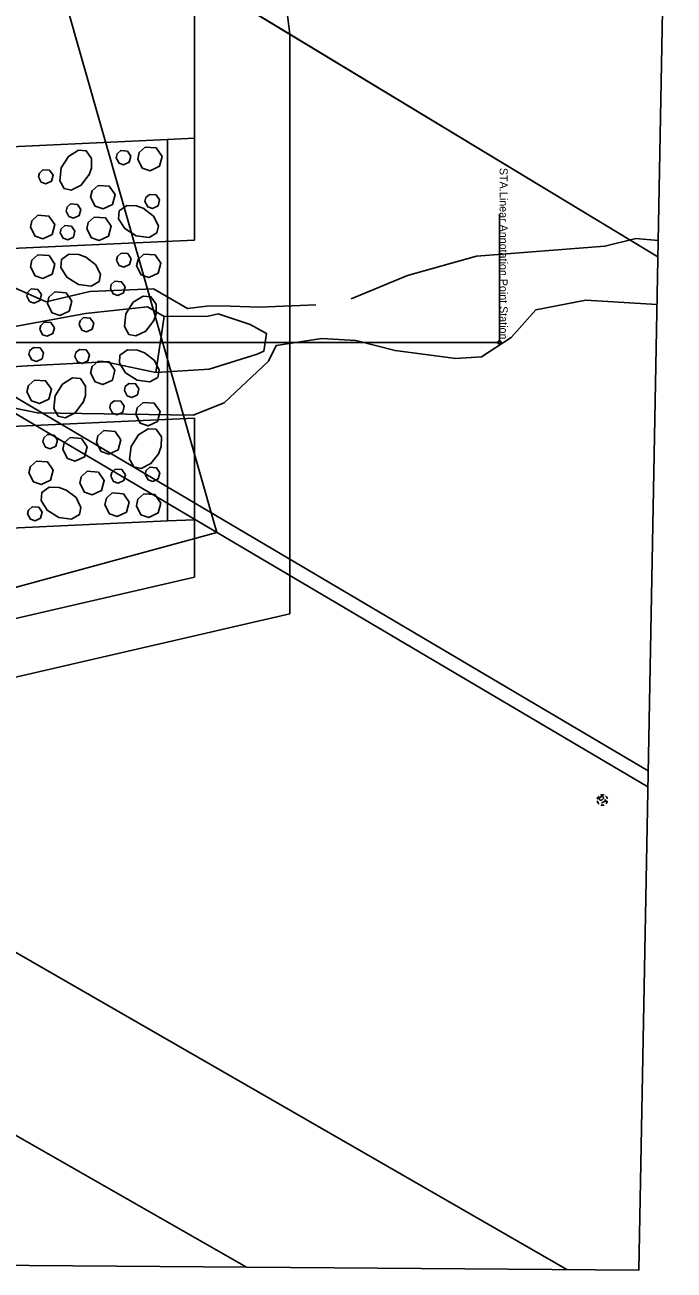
# Model space of a CAD drawing. Extents: x -1609 to 1184, y -412 to 394.
# Drawn here: x 44.9 to 78.9, y 262.3 to 327.7 of the extents above; entities that cross this region are included whole.
import ezdxf

# ---------------------------------------------------------------- set-up
doc = ezdxf.new("R2010")
doc.units = 0
for name, color, linetype in [('DR_P_Erosion_Control', 7, 'Continuous'), ('DT_P_Slope_Break_Line', 7, 'Continuous'), ('DT_X_Slope_Break_Line', 7, 'Continuous'), ('GE_P_Alignment_100_Cardinal_Points', 7, 'Continuous'), ('GE_P_CL_10', 7, 'Continuous'), ('HY_P_Water_Edge', 7, 'Continuous'), ('HY_X_Water_Edge', 7, 'Continuous'), ('PV_P_Shoulder', 7, 'Continuous'), ('RW_P_Const_Limits', 7, 'Continuous'), ('RW_X_Esmt_SH', 7, 'Continuous'), ('SH_Named_Boundary', 7, 'Continuous'), ('UT_X_Oil_Cells', 7, 'Continuous')]:
    doc.layers.add(name, color=color, linetype=linetype)

msp = doc.modelspace()

# ---------------------------------------------------------------- linework, layer by layer
at = {"layer": 'DR_P_Erosion_Control'}
for p, q in [((38.371, 320.994), (52.371, 321.648)), ((52.371, 321.648), (52.371, 301.62)), ((52.37, 312.649), (52.371, 312.649)), ((38.371, 300.989), (52.371, 301.62))]:
    msp.add_line(p, q, dxfattribs=at)
for points in [[(48.246, 319.785), (47.837, 319.247), (47.316, 318.991), (46.946, 319.072), (46.711, 319.478), (46.793, 320.15), (47.178, 320.758), (47.691, 321.081), (48.109, 321.05), (48.387, 320.652), (48.373, 320.139), (48.233, 319.758)], [(49.914, 321.065), (50.264, 321.04), (50.446, 320.774), (50.363, 320.463), (50.068, 320.322), (49.824, 320.407), (49.679, 320.691), (49.726, 320.894), (49.914, 321.064)], [(51.197, 321.244), (51.78, 321.203), (52.084, 320.76), (51.945, 320.241), (51.454, 320.007), (51.046, 320.148), (50.805, 320.621), (50.883, 320.959), (51.197, 321.244)], [(45.834, 320.057), (46.184, 320.033), (46.366, 319.766), (46.283, 319.455), (45.988, 319.314), (45.743, 319.399), (45.599, 319.683), (45.646, 319.886), (45.834, 320.057)], [(48.729, 319.237), (49.312, 319.196), (49.616, 318.753), (49.478, 318.233), (48.986, 317.999), (48.579, 318.141), (48.337, 318.614), (48.415, 318.952), (48.729, 319.237)], [(51.422, 318.767), (51.772, 318.743), (51.954, 318.477), (51.871, 318.165), (51.576, 318.025), (51.331, 318.11), (51.187, 318.394), (51.233, 318.597), (51.422, 318.767)], [(45.568, 317.665), (46.151, 317.625), (46.455, 317.181), (46.317, 316.662), (45.825, 316.428), (45.418, 316.569), (45.176, 317.043), (45.254, 317.381), (45.568, 317.665)], [(47.288, 318.266), (47.638, 318.242), (47.82, 317.975), (47.737, 317.664), (47.442, 317.523), (47.198, 317.608), (47.053, 317.892), (47.1, 318.095), (47.288, 318.266)], [(51.094, 318.038), (51.633, 317.628), (51.889, 317.108), (51.807, 316.738), (51.402, 316.503), (50.73, 316.585), (50.122, 316.969), (49.799, 317.483), (49.83, 317.901), (50.227, 318.179), (50.74, 318.165), (51.121, 318.024)], [(46.979, 317.123), (47.329, 317.099), (47.511, 316.833), (47.428, 316.521), (47.133, 316.381), (46.889, 316.466), (46.744, 316.75), (46.791, 316.953), (46.979, 317.123)], [(48.525, 317.575), (49.108, 317.534), (49.412, 317.091), (49.274, 316.571), (48.782, 316.337), (48.375, 316.478), (48.133, 316.952), (48.212, 317.29), (48.526, 317.575)], [(45.572, 315.588), (46.155, 315.548), (46.459, 315.104), (46.321, 314.585), (45.829, 314.351), (45.421, 314.492), (45.18, 314.965), (45.258, 315.304), (45.572, 315.588)], [(48.065, 315.482), (48.603, 315.073), (48.859, 314.552), (48.777, 314.183), (48.372, 313.948), (47.7, 314.029), (47.092, 314.414), (46.769, 314.928), (46.8, 315.346), (47.197, 315.623), (47.711, 315.609), (48.092, 315.469)], [(49.931, 315.68), (50.281, 315.656), (50.463, 315.39), (50.38, 315.078), (50.085, 314.938), (49.84, 315.023), (49.696, 315.307), (49.743, 315.51), (49.931, 315.68)], [(51.135, 315.631), (51.718, 315.591), (52.022, 315.147), (51.884, 314.628), (51.392, 314.394), (50.984, 314.535), (50.743, 315.009), (50.821, 315.347), (51.135, 315.631)], [(45.223, 313.801), (45.573, 313.777), (45.755, 313.511), (45.672, 313.199), (45.377, 313.059), (45.133, 313.143), (44.988, 313.427), (45.035, 313.631), (45.223, 313.801)], [(49.608, 314.204), (49.957, 314.18), (50.14, 313.913), (50.057, 313.602), (49.762, 313.462), (49.517, 313.546), (49.372, 313.83), (49.419, 314.033), (49.607, 314.204)], [(46.461, 313.646), (47.044, 313.605), (47.347, 313.162), (47.209, 312.642), (46.717, 312.408), (46.31, 312.55), (46.069, 313.023), (46.147, 313.361), (46.461, 313.645)], [(51.639, 312.131), (51.23, 311.592), (50.709, 311.336), (50.339, 311.418), (50.104, 311.823), (50.186, 312.495), (50.571, 313.103), (51.084, 313.426), (51.502, 313.395), (51.78, 312.998), (51.766, 312.485), (51.626, 312.104)], [(45.905, 312.057), (46.254, 312.033), (46.437, 311.767), (46.354, 311.455), (46.059, 311.315), (45.814, 311.4), (45.67, 311.684), (45.716, 311.887), (45.904, 312.057)], [(47.969, 312.3), (48.319, 312.275), (48.501, 312.009), (48.418, 311.698), (48.123, 311.557), (47.879, 311.642), (47.734, 311.926), (47.781, 312.129), (47.969, 312.3)], [(45.336, 310.735), (45.686, 310.711), (45.868, 310.445), (45.785, 310.133), (45.49, 309.993), (45.246, 310.078), (45.101, 310.362), (45.148, 310.565), (45.336, 310.735)], [(47.743, 310.629), (48.093, 310.604), (48.275, 310.338), (48.193, 310.027), (47.897, 309.886), (47.653, 309.971), (47.508, 310.255), (47.555, 310.458), (47.743, 310.628)], [(51.141, 310.458), (51.679, 310.049), (51.935, 309.529), (51.853, 309.159), (51.448, 308.924), (50.776, 309.005), (50.168, 309.39), (49.845, 309.904), (49.876, 310.322), (50.273, 310.599), (50.787, 310.586), (51.167, 310.445)], [(48.726, 310.015), (49.309, 309.975), (49.613, 309.531), (49.475, 309.012), (48.983, 308.778), (48.576, 308.919), (48.335, 309.392), (48.413, 309.731), (48.726, 310.015)], [(45.389, 309.02), (45.973, 308.98), (46.276, 308.536), (46.138, 308.017), (45.646, 307.783), (45.239, 307.924), (44.997, 308.398), (45.076, 308.736), (45.39, 309.02)], [(47.933, 307.832), (47.524, 307.293), (47.004, 307.038), (46.634, 307.119), (46.399, 307.525), (46.48, 308.196), (46.865, 308.805), (47.379, 309.128), (47.797, 309.096), (48.074, 308.699), (48.061, 308.186), (47.92, 307.805)], [(50.34, 308.845), (50.69, 308.821), (50.872, 308.554), (50.789, 308.243), (50.494, 308.102), (50.25, 308.187), (50.105, 308.471), (50.152, 308.674), (50.34, 308.845)], [(49.571, 307.934), (49.921, 307.909), (50.103, 307.643), (50.02, 307.332), (49.725, 307.191), (49.481, 307.276), (49.336, 307.56), (49.383, 307.763), (49.571, 307.934)], [(51.093, 307.848), (51.676, 307.807), (51.98, 307.364), (51.842, 306.844), (51.35, 306.61), (50.942, 306.751), (50.701, 307.225), (50.779, 307.563), (51.093, 307.847)], [(46.065, 306.153), (46.414, 306.128), (46.597, 305.862), (46.514, 305.551), (46.219, 305.41), (45.974, 305.495), (45.829, 305.779), (45.876, 305.982), (46.065, 306.152)], [(47.269, 306), (47.852, 305.959), (48.156, 305.516), (48.017, 304.996), (47.525, 304.762), (47.118, 304.904), (46.877, 305.377), (46.955, 305.715), (47.269, 305.999)], [(49.035, 306.367), (49.618, 306.326), (49.921, 305.883), (49.783, 305.363), (49.291, 305.129), (48.884, 305.271), (48.643, 305.744), (48.721, 306.082), (49.035, 306.366)], [(51.909, 305.168), (51.499, 304.63), (50.979, 304.374), (50.609, 304.455), (50.374, 304.861), (50.456, 305.532), (50.841, 306.141), (51.354, 306.464), (51.772, 306.433), (52.05, 306.036), (52.036, 305.522), (51.895, 305.141)], [(45.487, 304.766), (46.07, 304.726), (46.373, 304.282), (46.235, 303.763), (45.743, 303.529), (45.336, 303.67), (45.095, 304.143), (45.173, 304.482), (45.487, 304.766)], [(48.16, 304.229), (48.743, 304.188), (49.047, 303.744), (48.909, 303.225), (48.417, 302.991), (48.009, 303.132), (47.768, 303.606), (47.846, 303.944), (48.16, 304.228)], [(49.631, 304.343), (49.981, 304.318), (50.163, 304.052), (50.08, 303.741), (49.785, 303.6), (49.54, 303.685), (49.396, 303.969), (49.442, 304.172), (49.631, 304.342)], [(51.438, 304.442), (51.788, 304.418), (51.97, 304.151), (51.887, 303.84), (51.592, 303.699), (51.347, 303.784), (51.203, 304.068), (51.249, 304.271), (51.438, 304.442)], [(47.032, 303.256), (47.57, 302.846), (47.826, 302.326), (47.745, 301.956), (47.339, 301.721), (46.667, 301.802), (46.059, 302.187), (45.736, 302.701), (45.767, 303.119), (46.164, 303.397), (46.678, 303.383), (47.059, 303.242)], [(49.474, 303.094), (50.057, 303.054), (50.361, 302.61), (50.223, 302.091), (49.731, 301.857), (49.323, 301.998), (49.082, 302.471), (49.16, 302.81), (49.474, 303.094)], [(51.126, 303.044), (51.709, 303.003), (52.013, 302.56), (51.875, 302.041), (51.383, 301.807), (50.976, 301.948), (50.734, 302.421), (50.813, 302.76), (51.126, 303.044)], [(45.263, 302.366), (45.613, 302.341), (45.795, 302.075), (45.712, 301.764), (45.417, 301.623), (45.172, 301.708), (45.027, 301.992), (45.074, 302.195), (45.263, 302.366)]]:
    msp.add_lwpolyline(points, dxfattribs=at)
at = {"layer": 'DT_P_Slope_Break_Line'}
for p, q in [((52.371, 321.648), (53.787, 321.714)), ((52.371, 301.622), (53.787, 301.684)), ((53.787, 298.664), (38.367, 295.104))]:
    msp.add_line(p, q, dxfattribs=at)
at = {"layer": 'DT_X_Slope_Break_Line'}
for p, q in [((53.787, 328.244), (53.787, 321.714)), ((53.787, 321.714), (53.787, 316.354)), ((53.787, 301.684), (53.787, 307.014)), ((53.787, 298.664), (53.787, 301.684))]:
    msp.add_line(p, q, dxfattribs=at)
at = {"layer": 'GE_P_Alignment_100_Cardinal_Points'}
msp.add_line((69.787, 310.994), (69.787, 317.744), dxfattribs=at)
msp.add_circle((69.787, 310.994), 0.09, dxfattribs=at)
at = {"layer": 'GE_P_CL_10'}
msp.add_line((-80.213, 310.994), (69.787, 310.994), dxfattribs=at)
at = {"layer": 'HY_P_Water_Edge'}
for p, q in [((38.371, 315.661), (53.787, 316.354)), ((38.371, 306.328), (53.787, 307.014))]:
    msp.add_line(p, q, dxfattribs=at)
at = {"layer": 'HY_X_Water_Edge'}
for points in [[(60.145, 312.974), (57.195, 312.853), (55.159, 312.911), (54.439, 312.892), (53.412, 312.777), (51.627, 313.806), (48.297, 313.659), (46.011, 313.129), (44.122, 313.972), (40.454, 313.758), (35.918, 314.931), (32.49, 315.433), (28.979, 316.216), (27.051, 316.488)], [(78.112, 316.35), (76.943, 316.452), (75.319, 316.046), (68.584, 315.525), (64.952, 314.51), (62.007, 313.279)], [(23.549, 310.595), (25.818, 310.667), (32.279, 310.94), (37.913, 308.88), (40.334, 308.052), (41.523, 308.119), (45.547, 307.291), (53.721, 307.181), (55.339, 307.828), (57.661, 310.018), (58.073, 310.835), (60.472, 311.191), (62.256, 311.092), (64.311, 310.563), (67.493, 310.158), (68.836, 310.233), (70.401, 311.258), (71.7, 312.707), (74.323, 313.207), (78.049, 312.979)]]:
    msp.add_lwpolyline(points, dxfattribs=at)
msp.add_lwpolyline([(42.228, 311.787), (42.565, 309.599), (45.031, 309.764), (49.097, 309.982), (51.765, 309.419), (54.552, 309.594), (57.078, 310.382), (57.415, 310.534), (57.564, 311.466), (56.713, 311.929), (55.034, 312.487), (54.508, 312.375), (52.195, 312.349), (51.321, 312.858), (48.074, 312.512), (44.171, 311.801)], close=True, dxfattribs=at)
at = {"layer": 'PV_P_Shoulder'}
msp.add_line((51.765, 309.419), (52.195, 312.349), dxfattribs=at)
at = {"layer": 'RW_P_Const_Limits'}
for p, q in [((54.887, 358.416), (58.787, 327.182)), ((45.142, 335.444), (54.963, 301.012)), ((58.787, 310.994), (58.787, 327.182)), ((58.787, 296.74), (58.787, 310.994)), ((54.963, 301.012), (21.803, 291.983)), ((58.787, 296.74), (38.367, 292.025))]:
    msp.add_line(p, q, dxfattribs=at)
at = {"layer": 'RW_X_Esmt_SH'}
msp.add_arc((1944.751, -814.821), 2221.626, 148.038145, 150.981457, dxfattribs=at)
at = {"layer": 'SH_Named_Boundary'}
for p, q in [((77.576, 287.66), (-46.532, 360.94)), ((-46.532, 360.94), (77.576, 287.66)), ((77.576, 287.66), (-46.532, 360.94)), ((-46.532, 360.94), (77.576, 287.66)), ((78.096, 315.49), (2.832, 361.064)), ((2.832, 361.064), (78.096, 315.49)), ((78.096, 315.49), (2.832, 361.064)), ((2.832, 361.064), (78.096, 315.49)), ((73.327, 262.327), (-86.107, 354.093)), ((-86.107, 354.093), (73.327, 262.327)), ((73.327, 262.327), (-86.107, 354.093)), ((-86.107, 354.093), (73.327, 262.327)), ((6.267, 330.647), (77.592, 288.501)), ((77.592, 288.501), (6.267, 330.647)), ((6.267, 330.647), (77.592, 288.501)), ((77.592, 288.501), (6.267, 330.647)), ((78.096, 315.49), (78.096, 315.49)), ((78.096, 315.49), (78.096, 315.49)), ((-10.972, 300.96), (56.516, 262.456)), ((56.516, 262.456), (-10.972, 300.96)), ((77.592, 288.501), (77.592, 288.501)), ((77.592, 288.501), (77.592, 288.501)), ((77.576, 287.66), (77.576, 287.66)), ((77.576, 287.66), (77.576, 287.66)), ((56.516, 262.456), (56.516, 262.456)), ((73.327, 262.327), (73.327, 262.327)), ((73.327, 262.327), (73.327, 262.327))]:
    msp.add_line(p, q, dxfattribs=at)
msp.add_lwpolyline([(-24.862, 360.994), (-85.817, 360.841), (-90.022, 262.992), (-75.962, 263.471), (77.102, 262.298), (78.946, 360.994)], close=True, dxfattribs=at)
at = {"layer": 'UT_X_Oil_Cells'}
msp.add_line((75.184, 286.977), (75.184, 286.977), dxfattribs=at)
for points in [[(75.226, 287.135), (75.222, 287.138), (75.217, 287.142), (75.208, 287.146), (75.203, 287.148), (75.192, 287.151), (75.182, 287.153), (75.177, 287.154), (75.168, 287.154), (75.147, 287.152), (75.128, 287.147), (75.112, 287.141), (75.09, 287.13), (75.068, 287.115), (75.054, 287.101), (75.044, 287.089), (75.039, 287.082), (75.034, 287.073), (75.029, 287.063), (75.027, 287.055), (75.024, 287.048), (75.023, 287.04), (75.022, 287.03), (75.024, 287.013), (75.026, 287.005), (75.035, 286.991), (75.04, 286.986), (75.045, 286.981), (75.052, 286.976), (75.062, 286.972), (75.067, 286.97), (75.073, 286.968), (75.081, 286.966), (75.09, 286.966), (75.096, 286.966), (75.103, 286.966), (75.109, 286.966), (75.122, 286.968), (75.135, 286.97), (75.15, 286.975), (75.162, 286.981), (75.164, 286.982), (75.175, 286.989), (75.185, 286.995), (75.197, 287.004), (75.208, 287.014), (75.216, 287.023), (75.225, 287.034), (75.232, 287.044), (75.238, 287.057), (75.241, 287.067), (75.244, 287.076), (75.245, 287.085), (75.245, 287.096), (75.243, 287.107), (75.239, 287.116), (75.233, 287.126), (75.226, 287.135)], [(75.312, 286.996), (75.38, 286.884)], [(75.346, 286.939), (75.141, 286.815)]]:
    msp.add_lwpolyline(points, dxfattribs=at)
for start, end in [(131.14856, 171.17086), (71.21226, 111.2038), (11.18934, 51.23775), (191.18934, 231.17898), (251.1431, 291.15805), (311.14856, 351.17086)]:
    msp.add_arc((75.184, 286.977), 0.27, start, end, dxfattribs=at)

# ---------------------------------------------------------------- texts
at = {"layer": 'GE_P_Alignment_100_Cardinal_Points'}
for s, p in [(' STA. ', (69.794, 320.311)), ('Linear Annotation.Point Station', (69.794, 318.893))]:
    msp.add_text(s, height=0.42, rotation=269.99994, dxfattribs=at).set_placement(p)

doc.saveas('drawing.dxf')
